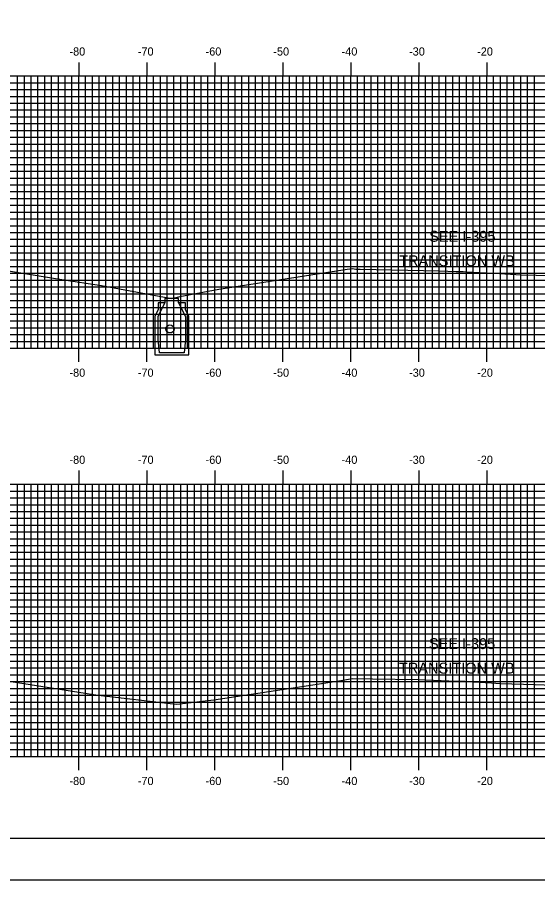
# Model space of a CAD drawing. Extents: x 854902 to 855245, y 364661 to 364881.
# Drawn here: x 854978.3 to 855054.8, y 364661.3 to 364788 of the extents above; entities that cross this region are included whole.
import ezdxf

# ---------------------------------------------------------------- set-up
doc = ezdxf.new("R2010")
doc.units = 0
for name, color, linetype in [('ANNOTATION', 7, 'Continuous'), ('BORDER', 7, 'Continuous'), ('H_V ANNOTATION', 7, 'Continuous'), ('M_Roadway_Centerline', 7, 'Continuous'), ('MAJOR', 7, 'Continuous'), ('MINOR', 7, 'Continuous'), ('PLOT BOUNDARY', 7, 'Continuous'), ('S_Drainage_CB', 7, 'Continuous'), ('S_Drainage_Invert', 7, 'Continuous'), ('S_Roadway_Centerline', 7, 'Continuous')]:
    doc.layers.add(name, color=color, linetype=linetype)

msp = doc.modelspace()

# ---------------------------------------------------------------- linework, layer by layer
at = {"layer": 'BORDER'}
msp.add_lwpolyline([(854917.75, 364667.37), (855237.75, 364667.37), (855237.75, 364877.37), (854917.75, 364877.37)], close=True, dxfattribs=at)
at = {"layer": 'MAJOR'}
for p, q in [((854987.35, 364781.37), (854987.35, 364779.37)), ((854997.35, 364781.37), (854997.35, 364779.37)), ((855007.35, 364781.37), (855007.35, 364779.37)), ((855017.35, 364781.37), (855017.35, 364779.37)), ((855027.35, 364781.37), (855027.35, 364779.37)), ((855037.35, 364781.37), (855037.35, 364779.37)), ((855047.35, 364781.37), (855047.35, 364779.37)), ((854927.35, 364779.37), (855207.35, 364779.37)), ((854927.35, 364779.37), (855207.35, 364779.37)), ((854987.35, 364739.37), (854987.35, 364779.37)), ((854997.35, 364739.37), (854997.35, 364779.37)), ((855007.35, 364739.37), (855007.35, 364779.37)), ((855017.35, 364739.37), (855017.35, 364779.37)), ((855027.35, 364739.37), (855027.35, 364779.37)), ((855037.35, 364739.37), (855037.35, 364779.37)), ((855047.35, 364739.37), (855047.35, 364779.37)), ((854927.35, 364774.37), (855207.35, 364774.37)), ((854927.35, 364769.37), (855207.35, 364769.37)), ((854927.35, 364764.37), (855207.35, 364764.37)), ((854927.35, 364759.37), (855207.35, 364759.37)), ((854927.35, 364754.37), (855207.35, 364754.37)), ((854927.35, 364749.37), (855207.35, 364749.37)), ((854927.35, 364744.37), (855207.35, 364744.37)), ((854927.35, 364739.37), (855207.35, 364739.37)), ((854927.35, 364739.37), (855207.35, 364739.37)), ((854987.35, 364737.37), (854987.35, 364739.37)), ((854997.35, 364737.37), (854997.35, 364739.37)), ((855007.35, 364737.37), (855007.35, 364739.37)), ((855017.35, 364737.37), (855017.35, 364739.37)), ((855027.35, 364737.37), (855027.35, 364739.37)), ((855037.35, 364737.37), (855037.35, 364739.37)), ((855047.35, 364737.37), (855047.35, 364739.37)), ((854987.35, 364721.37), (854987.35, 364719.37)), ((854997.35, 364721.37), (854997.35, 364719.37)), ((855007.35, 364721.37), (855007.35, 364719.37)), ((855017.35, 364721.37), (855017.35, 364719.37)), ((855027.35, 364721.37), (855027.35, 364719.37)), ((855037.35, 364721.37), (855037.35, 364719.37)), ((855047.35, 364721.37), (855047.35, 364719.37)), ((854927.35, 364719.37), (855207.35, 364719.37)), ((854927.35, 364719.37), (855207.35, 364719.37)), ((854987.35, 364679.37), (854987.35, 364719.37)), ((854997.35, 364679.37), (854997.35, 364719.37)), ((855007.35, 364679.37), (855007.35, 364719.37)), ((855017.35, 364679.37), (855017.35, 364719.37)), ((855027.35, 364679.37), (855027.35, 364719.37)), ((855037.35, 364679.37), (855037.35, 364719.37)), ((855047.35, 364679.37), (855047.35, 364719.37)), ((854927.35, 364714.37), (855207.35, 364714.37)), ((854927.35, 364709.37), (855207.35, 364709.37)), ((854927.35, 364704.37), (855207.35, 364704.37)), ((854927.35, 364699.37), (855207.35, 364699.37)), ((854927.35, 364694.37), (855207.35, 364694.37)), ((854927.35, 364689.37), (855207.35, 364689.37)), ((854927.35, 364684.37), (855207.35, 364684.37)), ((854927.35, 364679.37), (855207.35, 364679.37)), ((854927.35, 364679.37), (855207.35, 364679.37)), ((854987.35, 364677.37), (854987.35, 364679.37)), ((854997.35, 364677.37), (854997.35, 364679.37)), ((855007.35, 364677.37), (855007.35, 364679.37)), ((855017.35, 364677.37), (855017.35, 364679.37)), ((855027.35, 364677.37), (855027.35, 364679.37)), ((855037.35, 364677.37), (855037.35, 364679.37)), ((855047.35, 364677.37), (855047.35, 364679.37))]:
    msp.add_line(p, q, dxfattribs=at)
at = {"layer": 'MINOR'}
for p, q in [((854927.35, 364778.37), (855207.35, 364778.37)), ((854978.35, 364739.37), (854978.35, 364779.37)), ((854979.35, 364739.37), (854979.35, 364779.37)), ((854980.35, 364739.37), (854980.35, 364779.37)), ((854981.35, 364739.37), (854981.35, 364779.37)), ((854982.35, 364739.37), (854982.35, 364779.37)), ((854983.35, 364739.37), (854983.35, 364779.37)), ((854984.35, 364739.37), (854984.35, 364779.37)), ((854985.35, 364739.37), (854985.35, 364779.37)), ((854986.35, 364739.37), (854986.35, 364779.37)), ((854988.35, 364739.37), (854988.35, 364779.37)), ((854989.35, 364739.37), (854989.35, 364779.37)), ((854990.35, 364739.37), (854990.35, 364779.37)), ((854991.35, 364739.37), (854991.35, 364779.37)), ((854992.35, 364739.37), (854992.35, 364779.37)), ((854993.35, 364739.37), (854993.35, 364779.37)), ((854994.35, 364739.37), (854994.35, 364779.37)), ((854995.35, 364739.37), (854995.35, 364779.37)), ((854996.35, 364739.37), (854996.35, 364779.37)), ((854998.35, 364739.37), (854998.35, 364779.37)), ((854999.35, 364739.37), (854999.35, 364779.37)), ((855000.35, 364739.37), (855000.35, 364779.37)), ((855001.35, 364739.37), (855001.35, 364779.37)), ((855002.35, 364739.37), (855002.35, 364779.37)), ((855003.35, 364739.37), (855003.35, 364779.37)), ((855004.35, 364739.37), (855004.35, 364779.37)), ((855005.35, 364739.37), (855005.35, 364779.37)), ((855006.35, 364739.37), (855006.35, 364779.37)), ((855008.35, 364739.37), (855008.35, 364779.37)), ((855009.35, 364739.37), (855009.35, 364779.37)), ((855010.35, 364739.37), (855010.35, 364779.37)), ((855011.35, 364739.37), (855011.35, 364779.37)), ((855012.35, 364739.37), (855012.35, 364779.37)), ((855013.35, 364739.37), (855013.35, 364779.37)), ((855014.35, 364739.37), (855014.35, 364779.37)), ((855015.35, 364739.37), (855015.35, 364779.37)), ((855016.35, 364739.37), (855016.35, 364779.37)), ((855018.35, 364739.37), (855018.35, 364779.37)), ((855019.35, 364739.37), (855019.35, 364779.37)), ((855020.35, 364739.37), (855020.35, 364779.37)), ((855021.35, 364739.37), (855021.35, 364779.37)), ((855022.35, 364739.37), (855022.35, 364779.37)), ((855023.35, 364739.37), (855023.35, 364779.37)), ((855024.35, 364739.37), (855024.35, 364779.37)), ((855025.35, 364739.37), (855025.35, 364779.37)), ((855026.35, 364739.37), (855026.35, 364779.37)), ((855028.35, 364739.37), (855028.35, 364779.37)), ((855029.35, 364739.37), (855029.35, 364779.37)), ((855030.35, 364739.37), (855030.35, 364779.37)), ((855031.35, 364739.37), (855031.35, 364779.37)), ((855032.35, 364739.37), (855032.35, 364779.37)), ((855033.35, 364739.37), (855033.35, 364779.37)), ((855034.35, 364739.37), (855034.35, 364779.37)), ((855035.35, 364739.37), (855035.35, 364779.37)), ((855036.35, 364739.37), (855036.35, 364779.37)), ((855038.35, 364739.37), (855038.35, 364779.37)), ((855039.35, 364739.37), (855039.35, 364779.37)), ((855040.35, 364739.37), (855040.35, 364779.37)), ((855041.35, 364739.37), (855041.35, 364779.37)), ((855042.35, 364739.37), (855042.35, 364779.37)), ((855043.35, 364739.37), (855043.35, 364779.37)), ((855044.35, 364739.37), (855044.35, 364779.37)), ((855045.35, 364739.37), (855045.35, 364779.37)), ((855046.35, 364739.37), (855046.35, 364779.37)), ((855048.35, 364739.37), (855048.35, 364779.37)), ((855049.35, 364739.37), (855049.35, 364779.37)), ((855050.35, 364739.37), (855050.35, 364779.37)), ((855051.35, 364739.37), (855051.35, 364779.37)), ((855052.35, 364739.37), (855052.35, 364779.37)), ((855053.35, 364739.37), (855053.35, 364779.37)), ((855054.35, 364739.37), (855054.35, 364779.37)), ((854927.35, 364777.37), (855207.35, 364777.37)), ((854927.35, 364776.37), (855207.35, 364776.37)), ((854927.35, 364775.37), (855207.35, 364775.37)), ((854927.35, 364773.37), (855207.35, 364773.37)), ((854927.35, 364772.37), (855207.35, 364772.37)), ((854927.35, 364771.37), (855207.35, 364771.37)), ((854927.35, 364770.37), (855207.35, 364770.37)), ((854927.35, 364768.37), (855207.35, 364768.37)), ((854927.35, 364767.37), (855207.35, 364767.37)), ((854927.35, 364766.37), (855207.35, 364766.37)), ((854927.35, 364765.37), (855207.35, 364765.37)), ((854927.35, 364763.37), (855207.35, 364763.37)), ((854927.35, 364762.37), (855207.35, 364762.37)), ((854927.35, 364761.37), (855207.35, 364761.37)), ((854927.35, 364760.37), (855207.35, 364760.37)), ((854927.35, 364758.37), (855207.35, 364758.37)), ((854927.35, 364757.37), (855207.35, 364757.37)), ((854927.35, 364756.37), (855207.35, 364756.37)), ((854927.35, 364755.37), (855207.35, 364755.37)), ((854927.35, 364753.37), (855207.35, 364753.37)), ((854927.35, 364752.37), (855207.35, 364752.37)), ((854927.35, 364751.37), (855207.35, 364751.37)), ((854927.35, 364750.37), (855207.35, 364750.37)), ((854927.35, 364748.37), (855207.35, 364748.37)), ((854927.35, 364747.37), (855207.35, 364747.37)), ((854927.35, 364746.37), (855207.35, 364746.37)), ((854927.35, 364745.37), (855207.35, 364745.37)), ((854927.35, 364743.37), (855207.35, 364743.37)), ((854927.35, 364742.37), (855207.35, 364742.37)), ((854927.35, 364741.37), (855207.35, 364741.37)), ((854927.35, 364740.37), (855207.35, 364740.37)), ((854978.35, 364679.37), (854978.35, 364719.37)), ((854979.35, 364679.37), (854979.35, 364719.37)), ((854980.35, 364679.37), (854980.35, 364719.37)), ((854981.35, 364679.37), (854981.35, 364719.37)), ((854982.35, 364679.37), (854982.35, 364719.37)), ((854983.35, 364679.37), (854983.35, 364719.37)), ((854984.35, 364679.37), (854984.35, 364719.37)), ((854985.35, 364679.37), (854985.35, 364719.37)), ((854986.35, 364679.37), (854986.35, 364719.37)), ((854988.35, 364679.37), (854988.35, 364719.37)), ((854989.35, 364679.37), (854989.35, 364719.37)), ((854990.35, 364679.37), (854990.35, 364719.37)), ((854991.35, 364679.37), (854991.35, 364719.37)), ((854992.35, 364679.37), (854992.35, 364719.37)), ((854993.35, 364679.37), (854993.35, 364719.37)), ((854994.35, 364679.37), (854994.35, 364719.37)), ((854995.35, 364679.37), (854995.35, 364719.37)), ((854996.35, 364679.37), (854996.35, 364719.37)), ((854998.35, 364679.37), (854998.35, 364719.37)), ((854999.35, 364679.37), (854999.35, 364719.37)), ((855000.35, 364679.37), (855000.35, 364719.37)), ((855001.35, 364679.37), (855001.35, 364719.37)), ((855002.35, 364679.37), (855002.35, 364719.37)), ((855003.35, 364679.37), (855003.35, 364719.37)), ((855004.35, 364679.37), (855004.35, 364719.37)), ((855005.35, 364679.37), (855005.35, 364719.37)), ((855006.35, 364679.37), (855006.35, 364719.37)), ((855008.35, 364679.37), (855008.35, 364719.37)), ((855009.35, 364679.37), (855009.35, 364719.37)), ((855010.35, 364679.37), (855010.35, 364719.37)), ((855011.35, 364679.37), (855011.35, 364719.37)), ((855012.35, 364679.37), (855012.35, 364719.37)), ((855013.35, 364679.37), (855013.35, 364719.37)), ((855014.35, 364679.37), (855014.35, 364719.37)), ((855015.35, 364679.37), (855015.35, 364719.37)), ((855016.35, 364679.37), (855016.35, 364719.37)), ((855018.35, 364679.37), (855018.35, 364719.37)), ((855019.35, 364679.37), (855019.35, 364719.37)), ((855020.35, 364679.37), (855020.35, 364719.37)), ((855021.35, 364679.37), (855021.35, 364719.37)), ((855022.35, 364679.37), (855022.35, 364719.37)), ((855023.35, 364679.37), (855023.35, 364719.37)), ((855024.35, 364679.37), (855024.35, 364719.37)), ((855025.35, 364679.37), (855025.35, 364719.37)), ((855026.35, 364679.37), (855026.35, 364719.37)), ((855028.35, 364679.37), (855028.35, 364719.37)), ((855029.35, 364679.37), (855029.35, 364719.37)), ((855030.35, 364679.37), (855030.35, 364719.37)), ((855031.35, 364679.37), (855031.35, 364719.37)), ((855032.35, 364679.37), (855032.35, 364719.37)), ((855033.35, 364679.37), (855033.35, 364719.37)), ((855034.35, 364679.37), (855034.35, 364719.37)), ((855035.35, 364679.37), (855035.35, 364719.37)), ((855036.35, 364679.37), (855036.35, 364719.37)), ((855038.35, 364679.37), (855038.35, 364719.37)), ((855039.35, 364679.37), (855039.35, 364719.37)), ((855040.35, 364679.37), (855040.35, 364719.37)), ((855041.35, 364679.37), (855041.35, 364719.37)), ((855042.35, 364679.37), (855042.35, 364719.37)), ((855043.35, 364679.37), (855043.35, 364719.37)), ((855044.35, 364679.37), (855044.35, 364719.37)), ((855045.35, 364679.37), (855045.35, 364719.37)), ((855046.35, 364679.37), (855046.35, 364719.37)), ((855048.35, 364679.37), (855048.35, 364719.37)), ((855049.35, 364679.37), (855049.35, 364719.37)), ((855050.35, 364679.37), (855050.35, 364719.37)), ((855051.35, 364679.37), (855051.35, 364719.37)), ((855052.35, 364679.37), (855052.35, 364719.37)), ((855053.35, 364679.37), (855053.35, 364719.37)), ((855054.35, 364679.37), (855054.35, 364719.37)), ((854927.35, 364718.37), (855207.35, 364718.37)), ((854927.35, 364717.37), (855207.35, 364717.37)), ((854927.35, 364716.37), (855207.35, 364716.37)), ((854927.35, 364715.37), (855207.35, 364715.37)), ((854927.35, 364713.37), (855207.35, 364713.37)), ((854927.35, 364712.37), (855207.35, 364712.37)), ((854927.35, 364711.37), (855207.35, 364711.37)), ((854927.35, 364710.37), (855207.35, 364710.37)), ((854927.35, 364708.37), (855207.35, 364708.37)), ((854927.35, 364707.37), (855207.35, 364707.37)), ((854927.35, 364706.37), (855207.35, 364706.37)), ((854927.35, 364705.37), (855207.35, 364705.37)), ((854927.35, 364703.37), (855207.35, 364703.37)), ((854927.35, 364702.37), (855207.35, 364702.37)), ((854927.35, 364701.37), (855207.35, 364701.37)), ((854927.35, 364700.37), (855207.35, 364700.37)), ((854927.35, 364698.37), (855207.35, 364698.37)), ((854927.35, 364697.37), (855207.35, 364697.37)), ((854927.35, 364696.37), (855207.35, 364696.37)), ((854927.35, 364695.37), (855207.35, 364695.37)), ((854927.35, 364693.37), (855207.35, 364693.37)), ((854927.35, 364692.37), (855207.35, 364692.37)), ((854927.35, 364691.37), (855207.35, 364691.37)), ((854927.35, 364690.37), (855207.35, 364690.37)), ((854927.35, 364688.37), (855207.35, 364688.37)), ((854927.35, 364687.37), (855207.35, 364687.37)), ((854927.35, 364686.37), (855207.35, 364686.37)), ((854927.35, 364685.37), (855207.35, 364685.37)), ((854927.35, 364683.37), (855207.35, 364683.37)), ((854927.35, 364682.37), (855207.35, 364682.37)), ((854927.35, 364681.37), (855207.35, 364681.37)), ((854927.35, 364680.37), (855207.35, 364680.37))]:
    msp.add_line(p, q, dxfattribs=at)
at = {"layer": 'PLOT BOUNDARY'}
msp.add_lwpolyline([(854901.56, 364661.25), (855241.56, 364661.25), (855241.56, 364881.25), (854901.56, 364881.25)], close=True, dxfattribs=at)
at = {"layer": 'S_Drainage_CB'}
for p, q in [((855000.02, 364746.01), (854999.03, 364746.01)), ((854999.03, 364746.01), (854999.03, 364745.03)), ((854999.03, 364744.01), (855000.02, 364746.01)), ((855003.04, 364746.01), (855002.02, 364746.01)), ((855002.02, 364746.01), (855003.04, 364744.01)), ((855003.04, 364745.03), (855003.04, 364746.01)), ((854999.03, 364745.03), (854998.54, 364744.01)), ((854998.54, 364744.01), (854998.54, 364738.37)), ((854999.03, 364740.7), (854999.03, 364744.01)), ((855003.53, 364744.01), (855003.04, 364745.03)), ((855003.04, 364744.01), (855003.04, 364740.7)), ((855003.53, 364738.37), (855003.53, 364744.01)), ((854999.2, 364738.69), (854999.03, 364740.7)), ((855003.04, 364740.7), (855002.87, 364738.69)), ((854998.54, 364738.37), (855003.53, 364738.37)), ((855002.87, 364738.69), (854999.2, 364738.69))]:
    msp.add_line(p, q, dxfattribs=at)
msp.add_lwpolyline([(855002.51, 364746.05), (855002.02, 364746.05), (855002.02, 364746.68), (855000.02, 364746.68), (855000.02, 364746.05), (854999.53, 364746.05)], dxfattribs=at)
at = {"layer": 'S_Drainage_Invert'}
msp.add_circle((855000.76, 364742.2), 0.6, dxfattribs=at)
at = {"layer": 'S_Roadway_Centerline'}
for points in [[(854976.1, 364750.89), (854984.86, 364749.46), (854990.68, 364748.57), (855000.51, 364746.77), (855001.05, 364746.69), (855002.23, 364746.97), (855007.95, 364748.03), (855023.7, 364750.5), (855026.8, 364750.98), (855027.59, 364751.07), (855028.11, 364750.99), (855028.75, 364750.97), (855040.38, 364750.74), (855042.85, 364750.64), (855043.86, 364750.66), (855044.26, 364750.58), (855049.24, 364750.34), (855052.42, 364750.16), (855061.2, 364749.94)], [(854975.5, 364690.69), (854988.29, 364688.65), (854989.5, 364688.46), (854990.21, 364688.36), (855001.21, 364687.1), (855001.76, 364687.07), (855007.22, 364687.7), (855021.77, 364689.89), (855025.6, 364690.49), (855027.6, 364690.84), (855030.53, 364690.78), (855037.27, 364690.68), (855041.75, 364690.49), (855044.13, 364690.43), (855044.38, 364690.4), (855048.06, 364690.17), (855049.33, 364690.1), (855054.48, 364689.93), (855065.13, 364689.56)]]:
    msp.add_lwpolyline(points, dxfattribs=at)

# ---------------------------------------------------------------- texts
at = {"layer": 'ANNOTATION'}
for s, p in [('SEE I-395 ', (855038.88, 364755.01)), ('TRANSITION WB', (855034.47, 364751.41)), ('SEE I-395 ', (855038.84, 364695.15)), ('TRANSITION WB', (855034.43, 364691.55))]:
    msp.add_text(s, height=1.6, dxfattribs=at).set_placement(p)
at = {"layer": 'H_V ANNOTATION'}
for s, p in [('-80', (854985.98, 364782.37)), ('-70', (854996.03, 364782.37)), ('-60', (855006, 364782.37)), ('-50', (855015.96, 364782.37)), ('-40', (855026, 364782.37)), ('-30', (855035.92, 364782.37)), ('-20', (855045.93, 364782.37)), ('-80', (854985.98, 364735.17)), ('-70', (854996.03, 364735.17)), ('-60', (855006, 364735.17)), ('-50', (855015.96, 364735.17)), ('-40', (855026, 364735.17)), ('-30', (855035.92, 364735.17)), ('-20', (855045.93, 364735.17)), ('-80', (854985.98, 364722.37)), ('-70', (854996.03, 364722.37)), ('-60', (855006, 364722.37)), ('-50', (855015.96, 364722.37)), ('-40', (855026, 364722.37)), ('-30', (855035.92, 364722.37)), ('-20', (855045.93, 364722.37)), ('-80', (854985.98, 364675.17)), ('-70', (854996.03, 364675.17)), ('-60', (855006, 364675.17)), ('-50', (855015.96, 364675.17)), ('-40', (855026, 364675.17)), ('-30', (855035.92, 364675.17)), ('-20', (855045.93, 364675.17))]:
    msp.add_text(s, height=1.2, dxfattribs=at).set_placement(p)
at = {"layer": 'M_Roadway_Centerline'}
for s, p in [('C', (855043.85, 364750.66)), ('L', (855043.86, 364750.65)), ('C', (855044.13, 364690.43)), ('L', (855044.13, 364690.42))]:
    msp.add_text(s, height=0.0146, dxfattribs=at).set_placement(p)

doc.saveas('drawing.dxf')
